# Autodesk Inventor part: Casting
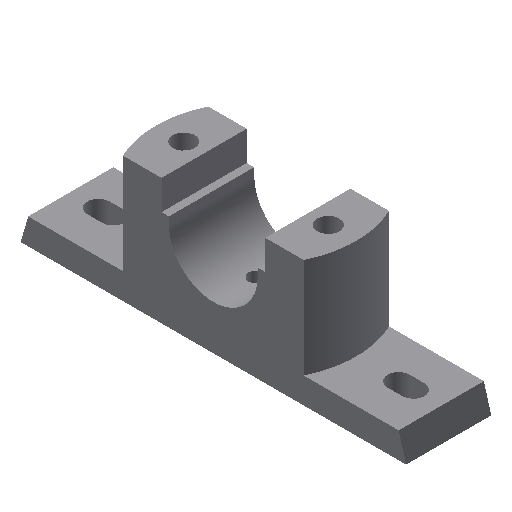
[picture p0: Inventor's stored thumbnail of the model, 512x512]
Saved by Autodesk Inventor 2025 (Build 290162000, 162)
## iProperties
Created: 2009-04
Part Number: Casting
Document SubType Name: Modeling
Designer: Sham
Density: 1 g/cm^3
Material: Generic
Appearance: Default
Author: Sham
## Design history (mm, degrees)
sketch "Sketch1"
  geometry: L1 (-104, 0)-(104, 0); L2 (-104, 0)-(-100, 14); L3 (-100, 14)-(100, 14); L4 (100, 14)-(104, 0); 1 further point
  constraints: 8 end point, 1 horizontal, 1 midpoint, 1 parallel, 1 other
  dimensions: "d0" = 208 distance of L1.start L1.end; "d1" = 104 distance of L1.end point (0, 0); "d2" = 4 horizontal distance of L1.start L2.end; "d3" = 4 horizontal distance of L1.end L3.end; "d10" = 14 distance between parallel lines of L1 L3
extrude "Extrusion1" new body sketch "Sketch1" stored distance "d4" = 46; taper "d5" = 0 deg
sketch "Sketch2"
  geometry: L1 (51.143, 46)-(148.857, 46); L2 (148.857, 0)-(51.143, 0); A1 r 54 centre (100, 23) between (51.143, 46) and (51.143, 0); A2 r 54 centre (100, 23) between (148.857, 0) and (148.857, 46)
  constraints: 4 end point, 4 point on circle, 2 centre point, 1 parallel
extrude "Extrusion2" join sketch "Sketch2" distance "d8" = 54; taper "d9" = 0 deg
sketch "Sketch3"
  geometry: L1 (-28, 68)-(-28, 52); L2 (-28, 52)-(-24, 52); L3 (28, 68)-(28, 52); L4 (28, 52)-(24, 52); L5 (-28, 68)-(28, 68); L6 (-100, 14)-(-48.857, 14) reference; L7 (0, 48)-(0, 19); L8 (48.857, 14)-(100, 14) reference; L9 (48.857, 68)-(-48.857, 68) reference; L10 (-24, 48)-(-24, 52); L11 (24, 48)-(24, 52); A1 r 24 centre (0, 48) between (-24, 48) and (24, 48); 1 further point
  constraints: 16 end point, 5 perpendicular, 2 point on circle, 2 symmetric about line, 1 centre point, 1 tangent, 1 vertical alignment, 1 other
  dimensions: "d11" = 16 distance of L1.start L1.end; "d16" = 24 radius of A1; "d17" = 16 distance of L3.start L3.end; "d52" = 56 distance between parallel lines of L1 L3; "d54" = 54 distance between parallel lines of L8 L9 (derived)
extrude "Extrusion3" cut sketch "Sketch3" distance "d18" = 54; taper "d19" = 0 deg
sketch "Sketch4"
  geometry: L1 (-23, 29)-(-15, 29); L2 (-15, 17)-(-23, 17); L3 (-185, 29)-(-177, 29); L4 (-177, 17)-(-185, 17); A1 r 6 centre (-15, 23) between (-15, 17) and (-15, 29); A2 r 6 centre (-23, 23) between (-23, 29) and (-23, 17); A3 r 6 centre (-177, 23) between (-177, 17) and (-177, 29); A4 r 6 centre (-185, 23) between (-185, 29) and (-185, 17)
  constraints: 8 end point, 8 point on circle, 8 tangent, 4 centre point, 3 parallel
  dimensions: "d20" = 8 distance of A1.centre A2.centre; "d21" = 6 radius of A1; "d24" = 6 radius of A3; "d25" = 8 distance of A4.centre A3.centre
extrude "Extrusion4" cut sketch "Sketch4" distance "d28" = 54; taper "d29" = 0 deg
sketch "Sketch5"
  geometry: L1 (208, 0)-(0, 0) reference; L2 (52, -10)-(78, -10); L3 (78, -10)-(78, -36); L4 (78, -36)-(52, -36); L5 (52, -36)-(52, -10); L6 (130, -10)-(156, -10); L7 (156, -10)-(156, -36); L8 (156, -36)-(130, -36); L9 (130, -36)-(130, -10); L10 (0, -46)-(208, -46) reference; L11 (104, -23)-(104, -46)
  constraints: 18 end point, 5 perpendicular, 4 parallel, 2 horizontal, 1 midpoint
  dimensions: "d30" = 26 distance of L2.start L2.end; "d31" = 10 distance between parallel lines of L2 L1; "d32" = 10 distance between parallel lines of L1 L6; "d65" = 26 distance between parallel lines of L3 L11; "d66" = 26 distance between parallel lines of L9 L11
extrude "Extrusion5" cut sketch "Sketch5" distance "d34" = 10; taper "d35" = 0 deg
sketch "Sketch6"
  geometry: L1 (148.857, 0)-(128, 0) reference; L2 (72, 0)-(51.143, 0) reference; L3 (0, 46)-(0, 0) reference; L4 (200, 46)-(200, 0) reference; C1 r 6 at (61, 23); C2 r 6 at (139, 23); 1 further point
  constraints: 2 centre point, 1 equal radius
  dimensions: "d36" = 12 diameter of C1; "d37" = 78 distance of C2.centre C1.centre; "d39" = 39 distance of C2.centre point (100, 23); "d58" = 39 distance of C1.centre point (100, 23); "d59" = 23 distance from line of L1 C2.centre; "d60" = 23 distance from line of L2 C1.centre; "d61" = 61 distance from line of L3 C1.centre; "d62" = 61 distance from line of L4 C2.centre (derived)
extrude "Extrusion6" cut sketch "Sketch6" extent not by distance; stored distance "d40" = 10; taper "d41" = 0 deg
workplane "Work Plane1"
sketch "Sketch7"
  geometry: L1 (-4, 46)-(204, 46) reference; L2 (-4, 0)-(-4, 46) reference; 1 further point
  dimensions: "d43" = 23 distance from line of L1 point (100, 23); "d44" = 104 distance from line of point (100, 23) L2
hole "Hole1" sketch "Sketch7" diameter "d45" = 8; stored, may be unused: countersink angle "d49" = 90 deg, drill point angle "d51" = 118 deg; dims "d46" = 6, "d47" = 8, "d48" = 16, "d50" = 8
body "Solid1"
other parameters: "d6" = 108, "d42" = -52
